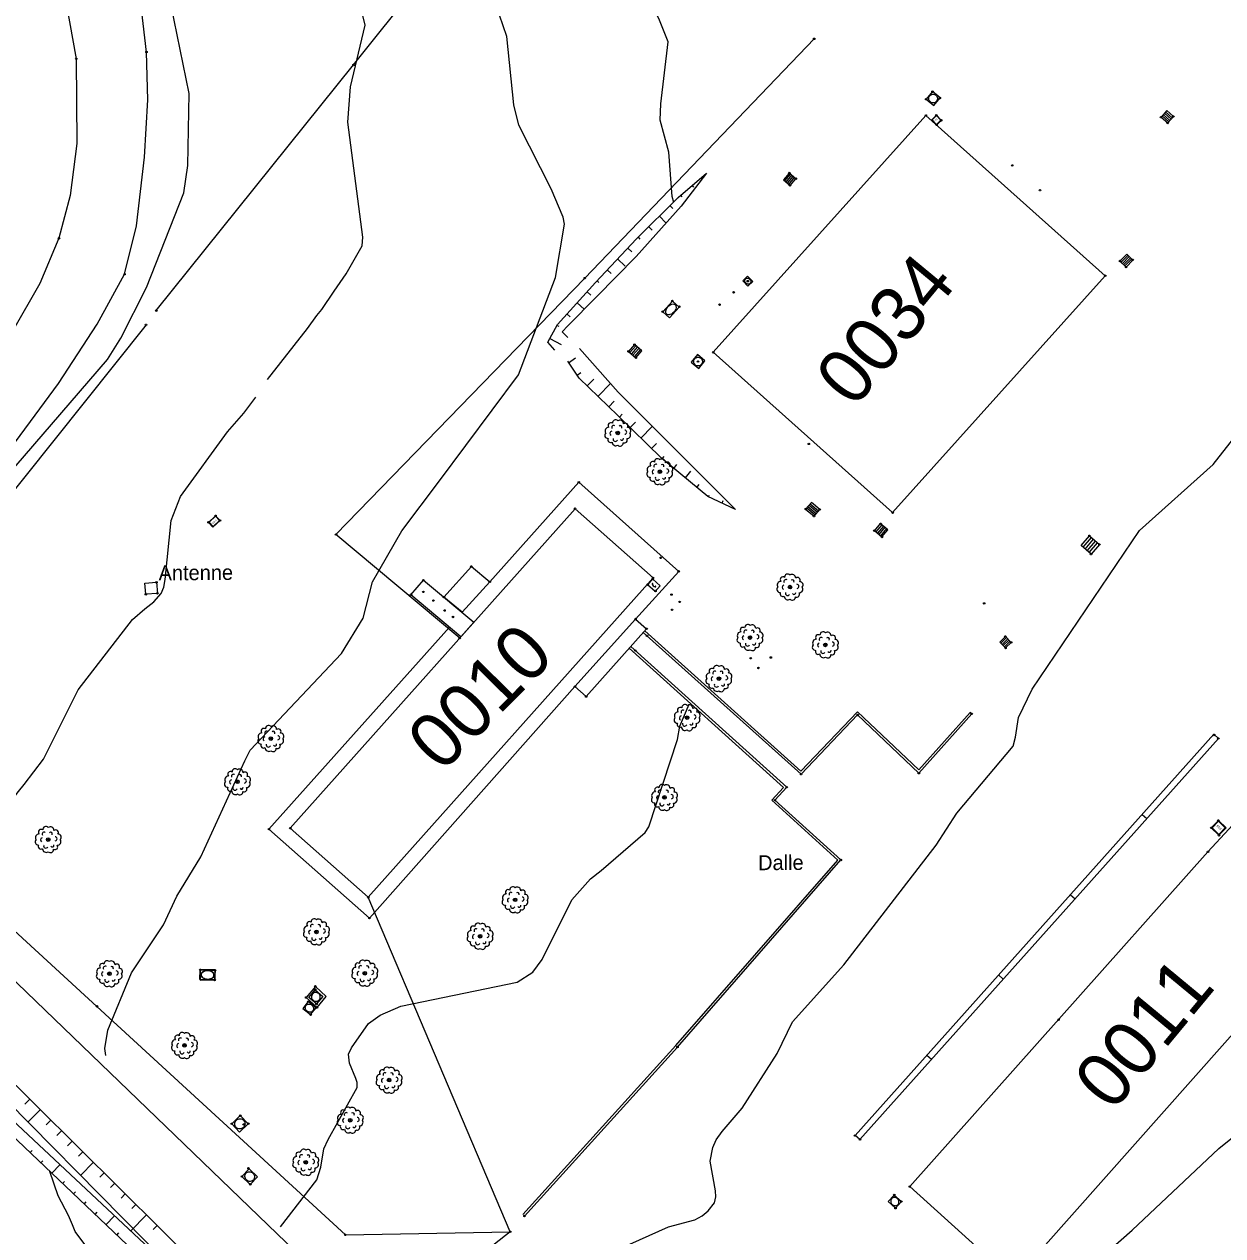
# Model space of a CAD drawing. Extents: x 344013 to 344423, y 298505 to 298795.
# Drawn here: x 344267.6 to 344347.8, y 298572.5 to 298653.6 of the extents above; entities that cross this region are included whole.
import ezdxf

# ---------------------------------------------------------------- set-up
doc = ezdxf.new("R2010")
doc.units = 0
for name, color, linetype in [('Default', 7, 'Continuous'), ('DH_CADRE -CARTOUCHE', 7, 'Continuous'), ('PC_CONCRETE', 7, 'Continuous'), ('PS_BOLT', 7, 'Continuous'), ('PS_CONST', 7, 'Continuous'), ('PS_WELD', 7, 'Continuous'), ('RES_ELECTRICITE', 7, 'Continuous'), ('TOPO_COURBE NIVEAU', 7, 'Continuous'), ('TOPO_POINT', 7, 'Continuous'), ('TOPO_TALUS-TERRAIN NATUREL', 7, 'Continuous'), ('VOIRIE_BORDURE', 7, 'Continuous'), ('VOIRIE_ESPACE VERT', 7, 'Continuous')]:
    doc.layers.add(name, color=color, linetype=linetype)

# ---------------------------------------------------------------- blocks, each defined once
blk = doc.blocks.new('R5')
at = {"layer": 'Default'}
for p, q in [((0, 1), (0, 0)), ((1, 1), (0, 1)), ((0.2, 1), (0.2, 0)), ((0.4, 1), (0.4, 0)), ((0.6, 1), (0.6, 0)), ((0.8, 1), (0.8, 0)), ((1, 0), (1, 1)), ((0, 0), (1, 0)), ((0.6, 0), (0.6, 0))]:
    blk.add_line(p, q, dxfattribs=at)
blk = doc.blocks.new('PTT3')
at = {"layer": 'Default'}
for p, q in [((0, 1), (1, 1)), ((0, 0), (0, 1)), ((1, 0), (0, 0)), ((1, 1), (1, 0))]:
    blk.add_line(p, q, dxfattribs=at)
for centre, radius, start, end in [((0.5, 0.7), 0.0417, 0, 180), ((0.5, 0.7), 0.0417, 180, 0), ((0.5, 0.29), 0.0417, 0, 180), ((0.5, 0.29), 0.0417, 180, 0), ((0.4, 0.49), 0.229, 297.2754, 62.7246)]:
    blk.add_arc(centre, radius, start, end, dxfattribs=at)
blk = doc.blocks.new('REG_INC')
at = {"layer": 'Default'}
for p, q in [((0, 1), (1, 1)), ((0, 0), (0, 1)), ((1, 1), (1, 0)), ((1, 0), (0, 0))]:
    blk.add_line(p, q, dxfattribs=at)
for centre, start, end in [((0.5, 0.498), 90.00577, 135.00577), ((0.5, 0.5), 45.00687, 90.00687), ((0.498, 0.5), 135.00554, 180.00554), ((0.501, 0.5), 180.00663, 225.00663), ((0.499, 0.498), 225.00686, 270.00686), ((0.499, 0.5), 270.00577, 315.00577), ((0.499, 0.499), 0.00663, 45.00663), ((0.501, 0.499), 315.00554, 0.00554)]:
    blk.add_arc(centre, 0.44, start, end, dxfattribs=at)
blk = doc.blocks.new('RES_ELECTRICITE')
at = {"layer": 'RES_ELECTRICITE'}
for points in [[(0, 0), (0, 1), (1, 1), (1, 0)], [(0.05, 0.05), (0.05, 0.95), (0.95, 0.95), (0.95, 0.05)]]:
    blk.add_lwpolyline(points, close=True, dxfattribs=at)
blk.add_text('EEC', height=0.2, dxfattribs=at).set_placement((0.24, 0.46))
blk = doc.blocks.new('POINT_DISPLAY')
at = {"layer": 'Default'}
blk.add_circle((0, 0), 0.05, dxfattribs=at)
blk = doc.blocks.new('ARB1')
at = {"layer": 'Default'}
blk.add_circle((0, 0), 0.122, dxfattribs=at)
for centre, radius, start, end in [((-0.153, 0.664), 0.211, 43.69255, 183.5969), ((0.139, 0.613), 0.241, 358.45835, 125.19284), ((-0.613, 0.139), 0.241, 88.45835, 215.19284), ((-0.471, 0.503), 0.183, 53.95544, 222.20655), ((-0.373, -0.024), 0.149, 103.70924, 242.34652), ((-0.276, 0.37), 0.134, 52.43963, 209.54959), ((0.164, 0.38), 0.112, 330.58954, 133.71274), ((0.501, 0.468), 0.183, 325.14445, 131.01755), ((0.458, 0.052), 0.137, 276.62143, 88.96702), ((0.613, -0.139), 0.241, 268.45835, 35.19284), ((0.664, 0.153), 0.211, 313.69255, 93.5969), ((-0.664, -0.153), 0.211, 133.69255, 273.5969), ((-0.478, -0.443), 0.19, 155.22426, 300.93774), ((-0.139, -0.613), 0.241, 178.45835, 305.19284), ((-0.163, -0.42), 0.148, 159.53711, 338.16632), ((0.153, -0.664), 0.211, 223.69255, 3.5969), ((0.271, -0.38), 0.112, 210.58954, 13.71274), ((0.448, -0.483), 0.188, 243.13234, 33.02965)]:
    blk.add_arc(centre, radius, start, end, dxfattribs=at)

msp = doc.modelspace()

# ---------------------------------------------------------------- linework, layer by layer
at = {"layer": 'DH_CADRE -CARTOUCHE'}
for points in [[(344325.673, 298620.896), (344339.895, 298636.741), (344327.896, 298647.47), (344313.669, 298631.62), (344325.673, 298620.896)], [(344357.784, 298596.545), (344357.784, 298596.545), (344333.772, 298569.519), (344326.819, 298575.802), (344346.771, 298598.198), (344350.978, 298602.747), (344357.784, 298596.545)]]:
    msp.add_lwpolyline(points, dxfattribs=at)
msp.add_lwpolyline([(344309.65, 298616.528), (344290.589, 298595.154), (344285.374, 298599.781), (344304.43, 298621.159)], close=True, dxfattribs=at)
at = {"layer": 'PS_BOLT'}
msp.add_lwpolyline([(344298.725, 298616.267), (344304.678, 298622.922), (344311.36, 298616.962), (344308.474, 298613.776), (344304.417, 298609.256), (344290.672, 298593.762), (344283.944, 298599.717), (344296.018, 298613.225)], dxfattribs=at)
for points in [[(344295.648, 298615.24), (344297.492, 298617.291), (344298.725, 298616.267), (344296.866, 298614.232)], [(344276.425, 298616.234), (344276.489, 298615.493), (344275.711, 298615.43), (344275.647, 298616.172)], [(344296.781, 298612.578), (344293.45, 298615.403), (344294.285, 298616.37), (344297.665, 298613.57)], [(344308.474, 298613.776), (344309.217, 298613.123), (344305.169, 298608.587), (344304.417, 298609.256)], [(344287.053, 298589.197), (344286.435, 298588.452), (344287.164, 298587.783), (344287.782, 298588.528)]]:
    msp.add_lwpolyline(points, close=True, dxfattribs=at)
at = {"layer": 'PS_WELD'}
for points in [[(344276.41, 298634.41), (344289.603, 298650.85), (344302.703, 298667.223)], [(344296.708, 298612.497), (344288.43, 298619.426), (344305.077, 298636.582), (344320.424, 298652.596)], [(344275.723, 298633.461), (344255.239, 298607.804), (344255.526, 298603.38), (344272.439, 298587.857), (344289.061, 298572.572), (344300.096, 298572.776)], [(344300.096, 298572.776), (344290.589, 298595.154)]]:
    msp.add_lwpolyline(points, dxfattribs=at)
at = {"layer": 'TOPO_COURBE NIVEAU'}
for points in [[(344311.039, 298641.643), (344310.915, 298642.036), (344310.707, 298645.003), (344310.128, 298647.144), (344310.154, 298648.255), (344310.648, 298652.392), (344310.029, 298653.959), (344308.514, 298656.851), (344307.575, 298659.779), (344307.41, 298664.78), (344307.707, 298668.001), (344307.725, 298669.134), (344307.859, 298669.472), (344310.352, 298673.167), (344310.534, 298673.805), (344311.258, 298678.736), (344311.907, 298680.765), (344312.138, 298682.865), (344312.117, 298684.902)], [(344295.365, 298623.026), (344300.65, 298630.117), (344303.118, 298636.618), (344303.721, 298640.189), (344303.62, 298640.654), (344302.829, 298642.567), (344300.656, 298646.813), (344300.327, 298648.182), (344299.855, 298652.754), (344299.119, 298654.896), (344298.331, 298659.485), (344298.396, 298660.21), (344298.477, 298661.501), (344297.026, 298665.383), (344296.113, 298669.359), (344295.917, 298672.878), (344296.635, 298675.355), (344298.522, 298679.722)], [(344275.76, 298635.963), (344278.264, 298642.294), (344278.527, 298644.111), (344278.614, 298648.943), (344277.411, 298654.833), (344275.85, 298657.266), (344275.573, 298657.664)], [(344283.847, 298629.801), (344286.536, 298633.219), (344287.142, 298634.092), (344287.482, 298634.477), (344288.309, 298635.709), (344289.122, 298636.882), (344290.18, 298638.738), (344290.221, 298639.328), (344289.217, 298647.023), (344289.402, 298649.392), (344290.377, 298653.521), (344290.126, 298654.607)], [(344252.625, 298604.895), (344257.025, 298612.454), (344273.147, 298631.145), (344274.046, 298632.575), (344275.76, 298635.963)], [(344263.934, 298593.221), (344263.793, 298593.473), (344263.66, 298594.141), (344263.767, 298596.618), (344264.217, 298598.12), (344264.959, 298599.315), (344267.189, 298602.229), (344267.56, 298602.692), (344268.868, 298604.405), (344271.176, 298609.031), (344274.827, 298613.739), (344275.638, 298614.454), (344276.252, 298614.924), (344276.741, 298615.491), (344276.915, 298615.899), (344277.01, 298616.419), (344277.411, 298620.371), (344278.019, 298621.967), (344281.165, 298626.296), (344282.277, 298627.546), (344283.081, 298628.63)], [(344305.309, 298570.703), (344310.679, 298573.102), (344312.434, 298573.579), (344312.922, 298573.846), (344313.332, 298574.176), (344313.758, 298574.709), (344313.836, 298575.103), (344313.814, 298575.504), (344313.455, 298577.504), (344313.645, 298578.416), (344313.867, 298578.935), (344314.261, 298579.485), (344315.601, 298581.04), (344317.958, 298584.71), (344318.984, 298586.815), (344322.414, 298590.641), (344328.577, 298598.654), (344329.957, 298600.783), (344333.733, 298605.27), (344333.892, 298605.868), (344334.098, 298607.19), (344335.015, 298609.077), (344342.194, 298619.707), (344347.121, 298624.114), (344349.225, 298626.809)], [(344273.026, 298584.578), (344272.972, 298585.042), (344273.162, 298586.27), (344274.744, 298590.108), (344276.882, 298593.308), (344277.789, 298595.233), (344279.398, 298597.874), (344282.337, 298604.276), (344282.7, 298604.999), (344288.8, 298611.472), (344290.26, 298613.838), (344290.87, 298616.27), (344292.835, 298619.673), (344295.365, 298623.026)], [(344284.721, 298573.101), (344287.158, 298576.252), (344287.418, 298577.109), (344287.625, 298578.321), (344287.902, 298578.942), (344289.843, 298582.418), (344289.852, 298582.772), (344289.765, 298583.031), (344289.335, 298584.064), (344289.28, 298584.653), (344289.462, 298585.086), (344290.598, 298586.721), (344291.378, 298587.279), (344292.764, 298587.875), (344293.535, 298588.031), (344300.556, 298589.482), (344301.596, 298590.142), (344302.219, 298590.998), (344304.208, 298594.992), (344305.462, 298596.382), (344306.178, 298596.94), (344309.121, 298599.495), (344309.366, 298599.88), (344311.287, 298605.708), (344311.446, 298606.605), (344312.07, 298608.076)], [(344336.006, 298567.895), (344341.693, 298572.872), (344347.492, 298578.337), (344349.752, 298580.151)]]:
    msp.add_lwpolyline(points, dxfattribs=at)
at = {"layer": 'TOPO_TALUS-TERRAIN NATUREL'}
for p, q in [((344313.015, 298643.426), (344313.051, 298643.385)), ((344311.502, 298642.118), (344311.576, 298642.032)), ((344312.259, 298642.772), (344312.342, 298642.676)), ((344310.779, 298641.427), (344310.966, 298641.238)), ((344310.067, 298640.725), (344310.504, 298640.281)), ((344309.354, 298640.023), (344309.585, 298639.789)), ((344308.642, 298639.321), (344308.763, 298639.197)), ((344307.953, 298638.596), (344308.22, 298638.345)), ((344307.268, 298637.866), (344307.776, 298637.39)), ((344305.9, 298636.407), (344306.027, 298636.288)), ((344306.584, 298637.137), (344306.852, 298636.886)), ((344305.229, 298635.665), (344305.475, 298635.444)), ((344304.561, 298634.921), (344305.029, 298634.501)), ((344303.893, 298634.176), (344304.093, 298633.997)), ((344303.235, 298633.425), (344303.346, 298633.362)), ((344302.746, 298632.552), (344303.494, 298632.133)), ((344303.998, 298630.925), (344304.463, 298631.244)), ((344304.564, 298630.101), (344304.809, 298630.269)), ((344305.243, 298629.372), (344305.679, 298629.823)), ((344305.962, 298628.677), (344306.791, 298629.534)), ((344306.681, 298627.981), (344307.036, 298628.348)), ((344307.4, 298627.285), (344307.588, 298627.477)), ((344308.113, 298626.585), (344308.471, 298626.949)), ((344308.827, 298625.884), (344309.582, 298626.653)), ((344309.541, 298625.183), (344309.864, 298625.512)), ((344310.259, 298624.487), (344310.384, 298624.639)), ((344311.032, 298623.852), (344311.246, 298624.112)), ((344311.805, 298623.218), (344312.17, 298623.662)), ((344312.578, 298622.583), (344312.734, 298622.773)), ((344313.358, 298621.958), (344313.402, 298622.053)), ((344314.264, 298621.534), (344314.34, 298621.697)), ((344267.942, 298581.647), (344267.62, 298581.322)), ((344268.652, 298580.943), (344267.824, 298580.107)), ((344269.362, 298580.239), (344269.05, 298579.924)), ((344270.073, 298579.535), (344269.766, 298579.225)), ((344270.783, 298578.831), (344270.481, 298578.526)), ((344267.967, 298578.071), (344268.099, 298578.209)), ((344271.493, 298578.127), (344271.196, 298577.827)), ((344268.692, 298577.381), (344268.825, 298577.521)), ((344269.417, 298576.692), (344269.955, 298577.258)), ((344272.203, 298577.423), (344271.335, 298576.546)), ((344272.913, 298576.719), (344272.627, 298576.429)), ((344270.141, 298576.003), (344270.277, 298576.146)), ((344273.624, 298576.015), (344273.342, 298575.73)), ((344270.866, 298575.314), (344271.003, 298575.458)), ((344271.591, 298574.625), (344271.729, 298574.771)), ((344274.334, 298575.311), (344274.057, 298575.031)), ((344272.315, 298573.936), (344272.455, 298574.083)), ((344275.044, 298574.606), (344274.772, 298574.333)), ((344273.04, 298573.247), (344273.605, 298573.841)), ((344275.754, 298573.902), (344274.688, 298572.827)), ((344276.464, 298573.198), (344276.203, 298572.935)), ((344273.765, 298572.558), (344273.907, 298572.708))]:
    msp.add_line(p, q, dxfattribs=at)
for points in [[(344303.078, 298631.766), (344302.606, 298632.302), (344303.261, 298633.472), (344305.792, 298636.293), (344308.534, 298639.215), (344311.331, 298641.971), (344313.229, 298643.611)], [(344313.229, 298643.611), (344311.518, 298641.404), (344308.506, 298638.024), (344305.858, 298635.338), (344303.943, 298633.398), (344303.572, 298632.997), (344303.952, 298632.607)], [(344304.722, 298631.882), (344307.301, 298628.957), (344315.17, 298621.11)], [(344315.17, 298621.11), (344313.316, 298621.978), (344310.207, 298624.53), (344307.285, 298627.398), (344304.71, 298629.887), (344303.934, 298631.018)], [(344261.171, 298586.591), (344261.462, 298586.802), (344261.885, 298586.943), (344262.288, 298586.932), (344262.541, 298586.882), (344262.809, 298586.735), (344279.551, 298570.139), (344295.871, 298554.464), (344296.985, 298553.14), (344298.042, 298551.584), (344299.067, 298549.893), (344299.43, 298549.138), (344299.767, 298548.322), (344300.085, 298546.934), (344300.44, 298543.115), (344300.582, 298541.707), (344300.685, 298541.186), (344300.87, 298540.983), (344301.161, 298540.78), (344301.681, 298540.61), (344303.077, 298540.314), (344306.776, 298539.876)], [(344278.14, 298568.397), (344260.685, 298584.995), (344260.562, 298585.212), (344260.507, 298585.527), (344260.496, 298585.774), (344260.599, 298586.003), (344260.73, 298586.167)], [(344261.801, 298586.214), (344278.783, 298568.994)], [(344299.009, 298539.876), (344299.007, 298540.023), (344298.804, 298542.305), (344298.347, 298544.206), (344297.069, 298547.321), (344296.487, 298549.751), (344296.128, 298551.133), (344295.589, 298552.785), (344294.926, 298554.057), (344294.294, 298554.751), (344278.783, 298568.994), (344261.096, 298585.55)], [(344272.852, 298570.283), (344270.983, 298572.788), (344270.803, 298573.237), (344270.536, 298573.866), (344269.838, 298575.181), (344269.288, 298576.815)]]:
    msp.add_lwpolyline(points, dxfattribs=at)
at = {"layer": 'VOIRIE_BORDURE'}
for points in [[(344265.711, 298623.939), (344269.866, 298629.528), (344272.446, 298633.509), (344274.289, 298636.845), (344275.079, 298640.087), (344275.631, 298644.676), (344275.835, 298648.511), (344275.757, 298651.713), (344275.152, 298656.894), (344274.334, 298660.713), (344273.252, 298664.267), (344271.939, 298667.741), (344266.911, 298680.387)], [(344267.481, 298665.493), (344268.766, 298661.408), (344270.195, 298655.984), (344271.053, 298651.262), (344271.086, 298645.598), (344270.649, 298642.118), (344269.897, 298639.251), (344268.61, 298636.233), (344266.758, 298632.993)], [(344308.994, 298612.872), (344319.549, 298603.389), (344323.327, 298607.358), (344327.426, 298603.458), (344330.963, 298607.432)], [(344309.094, 298612.984), (344319.541, 298603.598), (344323.322, 298607.57), (344327.418, 298603.674), (344330.851, 298607.531)], [(344300.928, 298573.931), (344311.167, 298585.233), (344321.996, 298597.643), (344317.583, 298601.648), (344318.376, 298602.511), (344308.053, 298611.82)], [(344301.039, 298573.83), (344311.28, 298585.134), (344322.206, 298597.655), (344317.795, 298601.658), (344318.589, 298602.521), (344308.154, 298611.931)], [(344330.963, 298607.432), (344330.851, 298607.531)], [(344286.346, 298570.863), (344252.815, 298603.162)], [(344300.096, 298572.776), (344297.561, 298570.779)]]:
    msp.add_lwpolyline(points, dxfattribs=at)

# ---------------------------------------------------------------- block references
at = {"layer": 'PC_CONCRETE'}
for name, p, xscale, yscale, rotation in [('REG_INC', (344327.917, 298648.555), 0.661062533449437, -0.6577505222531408, 50.45993999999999), ('R5', (344344.075, 298646.965), 0.5786150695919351, 0.596456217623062, 48.44223), ('R5', (344319.201, 298643.238), 0.581992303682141, 0.595954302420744, 139.58019000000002), ('R5', (344340.882, 298637.727), 0.574623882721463, 0.656226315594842, -44.66502000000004), ('REG_INC', (344315.995, 298636.051), 0.49313287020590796, -0.44231099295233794, 133.83080999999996), ('REG_INC', (344310.291, 298634.336), 0.9665851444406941, -0.6073917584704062, 47.94866999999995), ('R5', (344308.001, 298631.683), 0.6547748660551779, 0.6002194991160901, -40.827330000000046), ('REG_INC', (344312.191, 298630.956), 0.661062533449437, -0.6577505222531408, 50.45993999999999), ('R5', (344320.414, 298620.653), 0.5893209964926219, 0.7387061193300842, 49.449419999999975), ('R5', (344324.45, 298619.688), 0.661780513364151, 0.6235686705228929, -39.841920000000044), ('R5', (344338.839, 298619.34), 0.8856992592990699, -0.859586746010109, -40.836330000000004), ('R5', (344333.213, 298612.608), 0.559357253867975, -0.527402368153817, -45.38232), ('R5', (344347.466, 298605.786), 35.99130291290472, -0.4182752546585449, -131.78115000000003), ('REG_INC', (344280.314, 298589.622), 0.646982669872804, 0.984223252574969, 87.77978999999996), ('REG_INC', (344279.356, 298590.307), 1.000018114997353, -0.6851678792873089, 0.019439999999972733), ('REG_INC', (344287.128, 298588.02), 0.6651009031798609, 0.675724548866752, 49.57676999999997), ('REG_INC', (344287.096, 298587.769), 0.585969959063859, -0.6566664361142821, -128.08404), ('REG_INC', (344281.457, 298580.002), 0.7882220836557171, -0.7610881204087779, 43.543079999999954), ('REG_INC', (344282.701, 298575.949), 0.7685960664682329, -0.7000721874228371, 136.92590999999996), ('REG_INC', (344325.863, 298574.357), 0.593067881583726, 0.6491626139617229, 48.02885999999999)]:
    msp.add_blockref(name, p, dxfattribs=dict(at, xscale=xscale, yscale=yscale, rotation=rotation))
at = {"layer": 'PS_BOLT', "xscale": 0.508427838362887, "yscale": 0.6761410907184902, "rotation": -132.12576000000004}
msp.add_blockref('PTT3', (344309.624, 298616.451), dxfattribs=at)
at = {"layer": 'RES_ELECTRICITE'}
for p, xscale, yscale, rotation in [((344328.617, 298646.841), 0.437060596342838, 0.47653031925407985, 43.590509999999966), ((344280.375, 298620.685), 0.649144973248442, 0.43996025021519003, -136.9499927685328), ((344346.991, 298599.804), 0.7140719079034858, 0.6822477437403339, -44.364193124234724)]:
    msp.add_blockref('RES_ELECTRICITE', p, dxfattribs=dict(at, xscale=xscale, yscale=yscale, rotation=rotation))
at = {"layer": 'TOPO_POINT'}
for p in [(344320.424, 298652.596), (344271.053, 298651.262), (344275.757, 298651.713), (344289.603, 298650.85), (344327.917, 298648.555), (344328.338, 298649.064), (344328.834, 298648.632), (344327.896, 298647.47), (344328.594, 298647.478), (344328.934, 298647.143), (344343.62, 298647.351), (344344.075, 298646.965), (344344.459, 298647.398), (344328.617, 298646.841), (344318.758, 298643.615), (344333.675, 298644.125), (344319.201, 298643.238), (344318.809, 298642.789), (344335.534, 298642.465), (344269.897, 298639.251), (344340.882, 298637.727), (344341.291, 298637.323), (344341.733, 298637.809), (344274.289, 298636.845), (344305.077, 298636.582), (344315.984, 298636.381), (344339.895, 298636.741), (344315.036, 298635.636), (344310.938, 298635.053), (344314.094, 298634.812), (344276.41, 298634.41), (344310.291, 298634.336), (344311.411, 298634.671), (344275.723, 298633.461), (344308.001, 298631.683), (344308.403, 298632.129), (344313.669, 298631.62), (344308.496, 298631.255), (344312.655, 298631.002), (344307.285, 298626.223), (344320.066, 298625.492), (344310.102, 298623.628), (344304.678, 298622.922), (344304.43, 298621.159), (344319.861, 298621.142), (344320.797, 298621.1), (344279.901, 298620.242), (344280.375, 298620.685), (344280.676, 298620.366), (344320.414, 298620.653), (344324.871, 298620.15), (344325.673, 298620.896), (344288.43, 298619.426), (344324.45, 298619.688), (344338.839, 298619.34), (344324.959, 298619.264), (344339.509, 298618.761), (344310.156, 298617.871), (344338.944, 298618.113), (344297.492, 298617.291), (344311.36, 298616.962), (344276.425, 298616.234), (344294.285, 298616.37), (344298.725, 298616.267), (344309.283, 298616.073), (344309.624, 298616.451), (344309.65, 298616.528), (344275.711, 298615.43), (344276.489, 298615.493), (344293.45, 298615.403), (344294.278, 298615.589), (344295.648, 298615.24), (344309.81, 298615.647), (344310.879, 298615.412), (344318.807, 298615.911), (344294.951, 298615.011), (344311.42, 298614.921), (344331.797, 298614.818), (344295.697, 298614.346), (344296.26, 298613.914), (344308.474, 298613.776), (344310.92, 298614.393), (344309.217, 298613.123), (344296.708, 298612.497), (344309.24, 298612.651), (344316.133, 298612.534), (344321.172, 298612.043), (344333.213, 298612.608), (344333.605, 298612.21), (344308.45, 298611.664), (344317.526, 298611.202), (344333.229, 298611.839), (344316.184, 298611.152), (344316.694, 298610.499), (344314.05, 298609.786), (344304.417, 298609.256), (344305.169, 298608.587), (344311.924, 298607.175), (344323.327, 298607.358), (344330.963, 298607.432), (344284.074, 298605.774), (344347.187, 298606.013), (344347.466, 298605.786), (344319.549, 298603.389), (344327.426, 298603.458), (344281.84, 298602.885), (344318.589, 298602.521), (344310.405, 298601.835), (344317.795, 298601.658), (344347.464, 298600.296), (344283.944, 298599.717), (344285.374, 298599.781), (344346.991, 298599.804), (344347.502, 298599.305), (344269.18, 298599.016), (344322.206, 298597.655), (344346.771, 298598.198), (344290.589, 298595.154), (344300.417, 298594.986), (344290.672, 298593.762), (344287.125, 298592.842), (344298.076, 298592.547), (344279.356, 298590.307), (344280.339, 298590.268), (344273.273, 298590.041), (344280.314, 298589.622), (344290.36, 298590.078), (344287.051, 298588.971), (344287.053, 298589.197), (344272.439, 298587.857), (344286.435, 298588.452), (344286.583, 298588.178), (344287.096, 298587.769), (344287.128, 298588.02), (344287.164, 298587.783), (344286.734, 298587.307), (344336.773, 298586.963), (344278.297, 298585.243), (344311.28, 298585.134), (344291.988, 298582.921), (344282.028, 298580.545), (344281.457, 298580.002), (344282.254, 298579.958), (344282.568, 298580.008), (344289.389, 298580.242), (344323.157, 298579.212), (344323.162, 298579.214), (344323.485, 298578.948), (344286.407, 298577.423), (344282.139, 298576.473), (344282.577, 298577.023), (344282.701, 298575.949), (344326.819, 298575.802), (344325.782, 298575.237), (344326.259, 298574.798), (344325.863, 298574.357), (344301.039, 298573.83), (344289.061, 298572.572), (344300.096, 298572.776)]:
    msp.add_blockref('POINT_DISPLAY', p, dxfattribs=at)
at = {"layer": 'VOIRIE_ESPACE VERT'}
for p in [(344307.285, 298626.223), (344310.102, 298623.628), (344318.807, 298615.911), (344316.133, 298612.534), (344321.172, 298612.043), (344314.05, 298609.786), (344311.924, 298607.175), (344284.074, 298605.774), (344281.84, 298602.885), (344310.405, 298601.835), (344269.18, 298599.016), (344300.417, 298594.986), (344287.125, 298592.842), (344298.076, 298592.547), (344290.36, 298590.078), (344273.273, 298590.041), (344278.297, 298585.243), (344291.988, 298582.921), (344289.389, 298580.242), (344286.407, 298577.423)]:
    msp.add_blockref('ARB1', p, dxfattribs=at)

# ---------------------------------------------------------------- texts
at = {"layer": 'PS_CONST'}
for s, height, rotation, p in [('0034', 3.662, 50.36648, (344323.091, 298627.81)), ('Antenne', 1.0003, 0.3665, (344276.566, 298616.361)), ('0010', 3.662, 45.3665, (344295.515, 298603.436)), ('Dalle', 1.0003, 0.36649, (344316.675, 298596.968)), ('0011', 3.662, 50.36649, (344340.385, 298580.732))]:
    msp.add_text(s, height=height, rotation=rotation, dxfattribs=at).set_placement(p)

doc.saveas('drawing.dxf')
